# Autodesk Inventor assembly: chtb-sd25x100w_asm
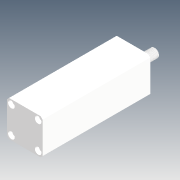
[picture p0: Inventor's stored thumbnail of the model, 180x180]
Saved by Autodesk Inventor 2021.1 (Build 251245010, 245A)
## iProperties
Company: Microsoft
Created: 2018-05
Part Number: chtb-sd25x100w_asm
Description: STEP AP214
Document SubType Name: Assembly
Designer: user
Title: chtb-sd25x100w_asm.STEP
Author: Windows
Revision Number: ÈÎºÎ
Sending System: SolidWorks 2015
Preprocessor: SwSTEP 2.0
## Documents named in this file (4)
- D:\Vault_2016\Projekty\Clamptek\Hydraulic\CHTB\CHTB-25\Inventor\chtb-sd25x100w\chtb-sd25x100w_asm.iam
- D:\Vault_2016\Projekty\Clamptek\Hydraulic\CHTB\CHTB-25\Inventor\chtb-sd25x100w\CHTB-25QG.ipt
- D:\Vault_2016\Projekty\Clamptek\Hydraulic\CHTB\CHTB-25\Inventor\chtb-sd25x100w\CHTB-SD25X100NBT.ipt
- D:\Vault_2016\Projekty\Clamptek\Hydraulic\CHTB\CHTB-25\Inventor\chtb-sd25x100w\CHTB-SD25X100WHSG.ipt
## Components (3 placed, 3 different names)
1. CHTB-25QG_1
2. CHTB-SD25X100NBT_2
3. CHTB-SD25X100WHSG_3
